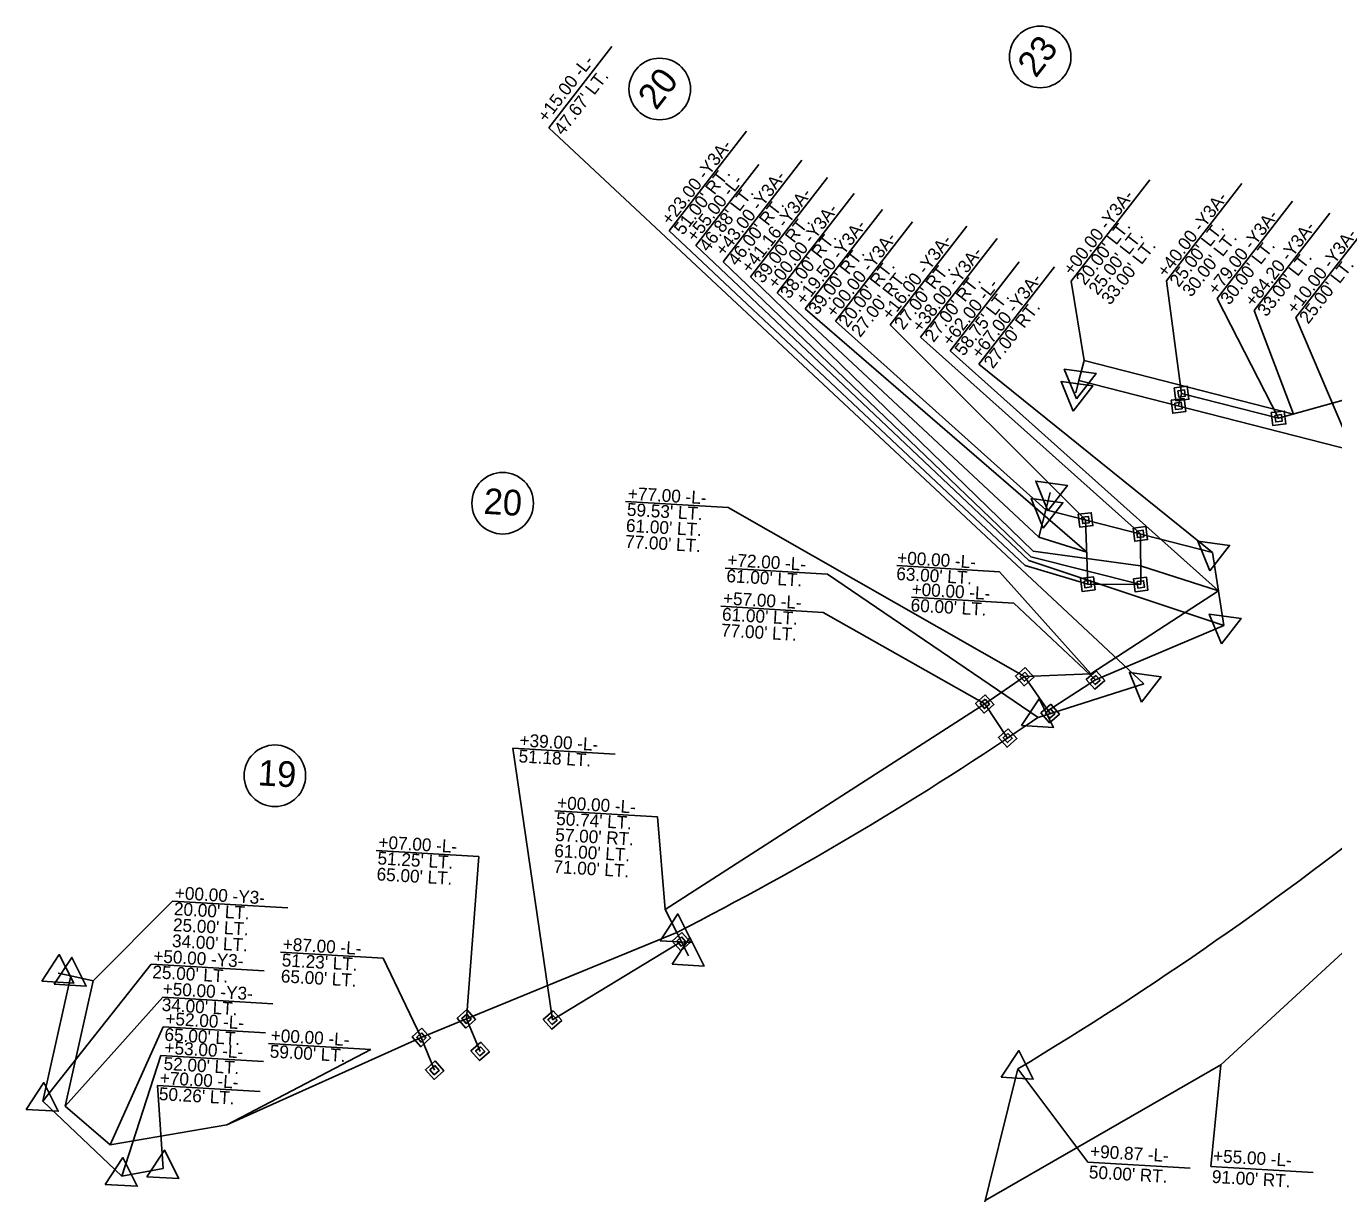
# Model space of a CAD drawing. Extents: x 2010883 to 2014849, y 442000 to 447413.
# Drawn here: x 2013533 to 2014042, y 445012 to 445467 of the extents above; entities that cross this region are included whole.
import ezdxf

# ---------------------------------------------------------------- set-up
doc = ezdxf.new("R2010")
doc.units = 0
for name, color, linetype in [('Prop Easement Construction', 7, 'Continuous'), ('Prop Easement Construction Station Offsets', 7, 'Continuous'), ('Prop Easement Permanent Drainage', 7, 'Continuous'), ('Prop Easement Permanent Drainage Station Offsets', 7, 'Continuous'), ('Prop Easement Permanent Utility', 7, 'Continuous'), ('Prop Easement Permanent Utility Station Offsets', 7, 'Continuous'), ('Prop Parcel Number CELL', 7, 'Continuous'), ('Prop Parcel Number Text', 7, 'Continuous'), ('Prop ROW Marker CELL', 7, 'Continuous'), ('Prop ROW Permanent Easement CELL', 7, 'Continuous'), ('Prop ROW RW Lines', 7, 'Continuous'), ('Prop ROW Station Offsets', 7, 'Continuous')]:
    doc.layers.add(name, color=color, linetype=linetype)

msp = doc.modelspace()

# ---------------------------------------------------------------- linework, layer by layer
at = {"layer": 'Prop Easement Construction'}
for p, q in [((2013942.7, 445328.8), (2013944.68, 445336.56)), ((2013944.68, 445336.56), (2014026.25, 445315.7)), ((2013927.09, 445267.77), (2013929.81, 445278.43)), ((2013927.09, 445267.77), (2013945.73, 445261.97)), ((2013966.71, 445256.6), (2013997.06, 445246.86)), ((2013947.4, 445214.55), (2013997.06, 445246.86)), ((2013921.55, 445213.41), (2013947.4, 445214.55)), ((2013781.47, 445122.66), (2013906.01, 445202.79)), ((2013997.94, 445062.16), (2014082.24, 445139.88)), ((2013786.01, 445113.75), (2013781.47, 445122.66)), ((2013704.09, 445080.08), (2013786.01, 445113.75)), ((2013549.97, 445096.83), (2013558.75, 445094.86)), ((2013558.75, 445094.86), (2013547.82, 445046.07)), ((2013610.79, 445038.76), (2013686.53, 445072.83)), ((2013906.21, 445009.36), (2013997.94, 445062.16)), ((2013547.82, 445046.07), (2013565.34, 445031.04)), ((2013565.34, 445031.04), (2013610.79, 445038.76))]:
    msp.add_line(p, q, dxfattribs=at)
at = {"layer": 'Prop Easement Construction Station Offsets'}
for p, q in [((2013814.73, 445369.18), (2013844.76, 445407.9)), ((2013825.15, 445363.01), (2013855.18, 445401.73)), ((2013836.1, 445356.73), (2013866.13, 445395.45)), ((2014011.02, 445356.11), (2014040.44, 445394.04)), ((2013892.56, 445340.31), (2013919.45, 445374.98)), ((2014026.25, 445315.7), (2014011.02, 445356.11)), ((2013997.06, 445246.86), (2013892.56, 445340.31)), ((2013871.82, 445256.66), (2013911.75, 445254.3)), ((2013947.4, 445214.55), (2013911.75, 445254.3)), ((2013547.82, 445046.07), (2013585.79, 445088.51)), ((2013585.79, 445088.51), (2013628.71, 445085.98)), ((2013565.34, 445031.04), (2013585.95, 445076.98)), ((2013585.95, 445076.98), (2013625.88, 445074.62)), ((2013626.99, 445070.51), (2013666.92, 445068.16)), ((2013610.79, 445038.76), (2013666.92, 445068.16)), ((2013997.94, 445062.16), (2013994.03, 445022.51)), ((2013994.03, 445022.51), (2014033.96, 445020.16))]:
    msp.add_line(p, q, dxfattribs=at)
for points in [[(2013814.73, 445369.18), (2013924.91, 445262.37), (2013924.91, 445262.37)], [(2013825.15, 445363.01), (2013927.09, 445267.77), (2013927.09, 445267.77)], [(2013836.1, 445356.73), (2013945.73, 445261.97), (2013945.73, 445261.97)], [(2013924.91, 445262.37), (2013966.71, 445256.6), (2013966.71, 445256.6)]]:
    msp.add_lwpolyline(points, dxfattribs=at)
at = {"layer": 'Prop Easement Permanent Drainage'}
for p, q in [((2013906.01, 445202.79), (2013921.55, 445213.41)), ((2013931.51, 445199.06), (2013921.55, 445213.41)), ((2013914.94, 445189.51), (2013906.01, 445202.79)), ((2013686.53, 445072.83), (2013704.09, 445080.08)), ((2013704.09, 445080.08), (2013709.44, 445067.41)), ((2013691.69, 445060.07), (2013686.53, 445072.83))]:
    msp.add_line(p, q, dxfattribs=at)
at = {"layer": 'Prop Easement Permanent Drainage Station Offsets'}
for p, q in [((2013766.11, 445281.64), (2013806.05, 445279.29)), ((2013806.05, 445279.29), (2013921.55, 445213.41)), ((2013803.17, 445240.82), (2013843.1, 445238.47)), ((2013843.1, 445238.47), (2013906.01, 445202.79)), ((2013668.96, 445145.74), (2013708.89, 445143.39)), ((2013704.09, 445080.08), (2013708.89, 445143.39)), ((2013631.67, 445106.02), (2013671.6, 445103.67)), ((2013686.53, 445072.83), (2013671.6, 445103.67))]:
    msp.add_line(p, q, dxfattribs=at)
at = {"layer": 'Prop Easement Permanent Utility'}
for p, q in [((2014020.47, 445314.08), (2014102.28, 445337)), ((2013981.45, 445318.89), (2013982.69, 445323.74)), ((2013982.69, 445323.74), (2014020.47, 445314.08)), ((2013946.15, 445249.48), (2013945.31, 445274.46)), ((2013966.76, 445249.37), (2013966.63, 445269.01)), ((2013946.15, 445249.48), (2013966.76, 445249.37)), ((2013949.15, 445212.12), (2013999.17, 445233.38)), ((2013930.68, 445200.27), (2013949.15, 445212.12)), ((2013737.64, 445079.65), (2013787.82, 445110.19))]:
    msp.add_line(p, q, dxfattribs=at)
at = {"layer": 'Prop Easement Permanent Utility Station Offsets'}
for p, q in [((2013783.11, 445387.15), (2013813.23, 445425.98)), ((2013804.09, 445375.05), (2013834.81, 445414.66)), ((2013976.76, 445367.63), (2014006.18, 445405.56)), ((2013996.51, 445360.7), (2014025.93, 445398.63)), ((2013921.7, 445256.66), (2013783.11, 445387.15)), ((2013869.18, 445350.53), (2013899.01, 445389)), ((2013881.02, 445345.72), (2013910.86, 445384.2)), ((2013923.98, 445260.15), (2013804.09, 445375.05)), ((2013976.76, 445367.63), (2013982.69, 445323.74)), ((2013996.51, 445360.7), (2014020.47, 445314.08)), ((2013869.18, 445350.53), (2013945.31, 445274.46)), ((2013881.02, 445345.72), (2013966.63, 445269.01)), ((2013966.76, 445249.37), (2013923.98, 445260.15)), ((2013946.15, 445249.48), (2013921.7, 445256.66)), ((2013877.42, 445244.4), (2013917.35, 445242.05)), ((2013949.15, 445212.12), (2013917.35, 445242.05)), ((2013722.15, 445185.59), (2013762.08, 445183.23)), ((2013737.64, 445079.65), (2013722.15, 445185.59))]:
    msp.add_line(p, q, dxfattribs=at)
at = {"layer": 'Prop Parcel Number CELL'}
for p, q in [((2013927.61, 445454.88), (2013927.61, 445454.88)), ((2013779.43, 445442.38), (2013779.43, 445442.38)), ((2013718.22, 445280.98), (2013718.22, 445280.98)), ((2013629.47, 445174.79), (2013629.47, 445174.79))]:
    msp.add_line(p, q, dxfattribs=at)
for centre in [(2013927.61, 445454.88), (2013779.43, 445442.38), (2013718.22, 445280.98), (2013629.47, 445174.79)]:
    msp.add_circle(centre, 12, dxfattribs=at)
at = {"layer": 'Prop ROW Marker CELL'}
for p, q in [((2013942.7, 445328.8), (2013942.7, 445328.8)), ((2013941.46, 445323.96), (2013941.46, 445323.96)), ((2013982.69, 445323.74), (2013982.69, 445323.74)), ((2013981.45, 445318.89), (2013981.45, 445318.89)), ((2014020.47, 445314.08), (2014020.47, 445314.08)), ((2013931.55, 445285.21), (2013931.55, 445285.21)), ((2013929.81, 445278.43), (2013929.81, 445278.43)), ((2013945.31, 445274.46), (2013945.31, 445274.46)), ((2013966.63, 445269.01), (2013966.63, 445269.01)), ((2013994.72, 445261.83), (2013994.72, 445261.83)), ((2013946.15, 445249.48), (2013946.15, 445249.48)), ((2013966.76, 445249.37), (2013966.76, 445249.37)), ((2013999.17, 445233.38), (2013999.17, 445233.38)), ((2013921.55, 445213.41), (2013921.55, 445213.41)), ((2013949.15, 445212.12), (2013949.15, 445212.12)), ((2013968.04, 445210.63), (2013968.04, 445210.63)), ((2013906.01, 445202.79), (2013906.01, 445202.79)), ((2013931.51, 445199.06), (2013931.51, 445199.06)), ((2013926.76, 445197.56), (2013926.76, 445197.56)), ((2013914.94, 445189.51), (2013914.94, 445189.51)), ((2013786.01, 445113.75), (2013786.01, 445113.75)), ((2013787.82, 445110.19), (2013787.82, 445110.19)), ((2013790.66, 445104.61), (2013790.66, 445104.61)), ((2013545.09, 445097.92), (2013545.09, 445097.92)), ((2013549.97, 445096.83), (2013549.97, 445096.83)), ((2013704.09, 445080.08), (2013704.09, 445080.08)), ((2013737.64, 445079.65), (2013737.64, 445079.65)), ((2013686.53, 445072.83), (2013686.53, 445072.83)), ((2013709.44, 445067.41), (2013709.44, 445067.41)), ((2013918.9, 445060.55), (2013918.9, 445060.55)), ((2013691.69, 445060.07), (2013691.69, 445060.07)), ((2013539.04, 445048.04), (2013539.04, 445048.04)), ((2013586.01, 445021.78), (2013586.01, 445021.78)), ((2013569.86, 445018.82), (2013569.86, 445018.82))]:
    msp.add_line(p, q, dxfattribs=at)
for points in [[(2013941.71, 445321.66), (2013937.01, 445333.22), (2013949.37, 445331.54)], [(2013940.47, 445316.82), (2013935.77, 445328.37), (2013948.13, 445326.69)], [(2013930.56, 445278.06), (2013925.86, 445289.62), (2013938.22, 445287.94)], [(2013928.83, 445271.28), (2013924.12, 445282.84), (2013936.49, 445281.16)], [(2013993.74, 445254.68), (2013989.03, 445266.24), (2014001.4, 445264.56)], [(2013998.18, 445226.24), (2013993.48, 445237.79), (2014005.84, 445236.11)], [(2013967.05, 445203.49), (2013962.35, 445215.05), (2013974.71, 445213.37)], [(2013920.31, 445194.33), (2013927.18, 445204.74), (2013932.79, 445193.59)], [(2013779.56, 445110.53), (2013786.43, 445120.94), (2013792.04, 445109.79)], [(2013784.21, 445101.38), (2013791.09, 445111.8), (2013796.69, 445100.65)], [(2013538.64, 445094.7), (2013545.51, 445105.11), (2013551.12, 445093.96)], [(2013543.52, 445093.6), (2013550.39, 445104.02), (2013556, 445092.87)], [(2013912.44, 445057.32), (2013919.32, 445067.73), (2013924.92, 445056.58)], [(2013532.59, 445044.81), (2013539.46, 445055.23), (2013545.07, 445044.08)], [(2013563.41, 445015.59), (2013570.28, 445026), (2013575.89, 445014.85)], [(2013579.56, 445018.55), (2013586.44, 445028.97), (2013592.04, 445017.82)]]:
    msp.add_lwpolyline(points, close=True, dxfattribs=at)
at = {"layer": 'Prop ROW Permanent Easement CELL'}
for points in [[(2013979.84, 445325.94), (2013984.89, 445326.58), (2013985.53, 445321.53), (2013980.48, 445320.89)], [(2013981.27, 445324.84), (2013983.79, 445325.16), (2013984.11, 445322.64), (2013981.58, 445322.32)], [(2013978.6, 445321.1), (2013983.66, 445321.74), (2013984.29, 445316.69), (2013979.24, 445316.05)], [(2013980.03, 445320), (2013982.55, 445320.32), (2013982.87, 445317.79), (2013980.35, 445317.47)], [(2014017.63, 445316.28), (2014022.68, 445316.92), (2014023.32, 445311.87), (2014018.27, 445311.23)], [(2014019.05, 445315.18), (2014021.57, 445315.5), (2014021.89, 445312.97), (2014019.37, 445312.65)], [(2013942.47, 445276.67), (2013947.52, 445277.31), (2013948.16, 445272.26), (2013943.11, 445271.62)], [(2013943.89, 445275.57), (2013946.42, 445275.88), (2013946.74, 445273.36), (2013944.21, 445273.04)], [(2013963.78, 445271.22), (2013968.83, 445271.86), (2013969.47, 445266.81), (2013964.42, 445266.17)], [(2013965.21, 445270.11), (2013967.73, 445270.43), (2013968.05, 445267.91), (2013965.52, 445267.59)], [(2013943.3, 445251.68), (2013948.36, 445252.32), (2013948.99, 445247.27), (2013943.94, 445246.63)], [(2013944.73, 445250.58), (2013947.25, 445250.9), (2013947.57, 445248.37), (2013945.05, 445248.05)], [(2013963.92, 445251.57), (2013968.97, 445252.21), (2013969.61, 445247.16), (2013964.56, 445246.52)], [(2013965.34, 445250.47), (2013967.87, 445250.79), (2013968.19, 445248.26), (2013965.66, 445247.94)], [(2013921.76, 445217), (2013925.14, 445213.2), (2013921.34, 445209.82), (2013917.96, 445213.62)], [(2013921.66, 445215.2), (2013923.35, 445213.3), (2013921.44, 445211.61), (2013919.75, 445213.51)], [(2013949.37, 445215.71), (2013952.75, 445211.91), (2013948.94, 445208.53), (2013945.56, 445212.33)], [(2013949.26, 445213.92), (2013950.95, 445212.01), (2013949.05, 445210.32), (2013947.36, 445212.22)], [(2013906.23, 445206.39), (2013909.61, 445202.58), (2013905.8, 445199.2), (2013902.42, 445203.01)], [(2013906.12, 445204.59), (2013907.81, 445202.69), (2013905.91, 445201), (2013904.22, 445202.9)], [(2013931.73, 445202.66), (2013935.11, 445198.85), (2013931.3, 445195.47), (2013927.92, 445199.27)], [(2013931.62, 445200.86), (2013933.31, 445198.96), (2013931.41, 445197.27), (2013929.72, 445199.17)], [(2013915.15, 445193.11), (2013918.53, 445189.3), (2013914.73, 445185.92), (2013911.34, 445189.73)], [(2013915.04, 445191.31), (2013916.73, 445189.41), (2013914.83, 445187.72), (2013913.14, 445189.62)], [(2013788.03, 445113.78), (2013791.42, 445109.97), (2013787.61, 445106.59), (2013784.23, 445110.4)], [(2013787.93, 445111.98), (2013789.62, 445110.08), (2013787.72, 445108.39), (2013786.03, 445110.29)], [(2013704.3, 445083.68), (2013707.69, 445079.87), (2013703.88, 445076.49), (2013700.5, 445080.3)], [(2013704.2, 445081.88), (2013705.89, 445079.98), (2013703.99, 445078.29), (2013702.3, 445080.19)], [(2013737.85, 445083.24), (2013741.23, 445079.44), (2013737.43, 445076.06), (2013734.04, 445079.86)], [(2013737.74, 445081.45), (2013739.43, 445079.54), (2013737.53, 445077.85), (2013735.84, 445079.76)], [(2013686.74, 445076.42), (2013690.13, 445072.62), (2013686.32, 445069.24), (2013682.94, 445073.04)], [(2013686.64, 445074.63), (2013688.33, 445072.72), (2013686.43, 445071.03), (2013684.73, 445072.94)], [(2013709.65, 445071.01), (2013713.03, 445067.2), (2013709.23, 445063.82), (2013705.85, 445067.62)], [(2013709.55, 445069.21), (2013711.24, 445067.31), (2013709.33, 445065.62), (2013707.64, 445067.52)], [(2013691.9, 445063.66), (2013695.28, 445059.85), (2013691.48, 445056.47), (2013688.1, 445060.28)], [(2013691.79, 445061.86), (2013693.49, 445059.96), (2013691.58, 445058.27), (2013689.89, 445060.17)]]:
    msp.add_lwpolyline(points, close=True, dxfattribs=at)
at = {"layer": 'Prop ROW RW Lines'}
for p, q in [((2013941.46, 445323.96), (2013942.7, 445328.8)), ((2013942.7, 445328.8), (2014049.27, 445301.55)), ((2013929.81, 445278.43), (2013931.55, 445285.21)), ((2013994.72, 445261.83), (2013929.81, 445278.43)), ((2013999.17, 445233.38), (2013994.72, 445261.83)), ((2013926.76, 445197.56), (2013968.04, 445210.63)), ((2013786.01, 445113.75), (2013790.66, 445104.61)), ((2013549.97, 445096.83), (2013539.04, 445048.04)), ((2013545.09, 445097.92), (2013549.97, 445096.83)), ((2013876.69, 444890.19), (2013918.9, 445060.55)), ((2013539.04, 445048.04), (2013569.86, 445018.82)), ((2013569.86, 445018.82), (2013586.01, 445021.78))]:
    msp.add_line(p, q, dxfattribs=at)
for radius, start, end in [(1350, 300.98467, 316.59253), (1239, 296.97975, 304.56042)]:
    msp.add_arc((2013223.9, 446217.91), radius, start, end, dxfattribs=at)
at = {"layer": 'Prop ROW Station Offsets'}
for p, q in [((2013736.26, 445427.3), (2013760.78, 445458.9)), ((2013736.26, 445427.3), (2013968.04, 445210.63)), ((2013793.46, 445381.36), (2013817.97, 445412.97)), ((2013939.72, 445367.5), (2013970.36, 445407.01)), ((2013847.82, 445351.9), (2013877.85, 445390.62)), ((2014027.25, 445353.3), (2014056.66, 445391.23)), ((2013793.46, 445381.36), (2013923.16, 445258.66)), ((2013903.74, 445335.19), (2013933.15, 445373.12)), ((2013939.72, 445367.5), (2013944.68, 445336.56)), ((2013929.81, 445278.43), (2013847.82, 445351.9)), ((2014027.25, 445353.3), (2014049.27, 445301.55)), ((2013903.74, 445335.19), (2013994.72, 445261.83)), ((2013804.87, 445255.73), (2013844.8, 445253.37)), ((2013923.16, 445258.66), (2013999.17, 445233.38)), ((2013844.8, 445253.37), (2013926.76, 445197.56)), ((2013738.57, 445161.13), (2013778.5, 445158.78)), ((2013778.5, 445158.78), (2013781.47, 445122.66)), ((2013589.63, 445125.96), (2013558.75, 445094.86)), ((2013589.63, 445125.96), (2013634.55, 445123.31)), ((2013539.04, 445048.04), (2013581.25, 445101.35)), ((2013581.25, 445101.35), (2013625.35, 445098.75)), ((2013569.86, 445018.82), (2013585.1, 445065.83)), ((2013585.1, 445065.83), (2013625.03, 445063.48)), ((2013946.12, 445024.29), (2013918.9, 445060.55)), ((2013583.79, 445054.12), (2013623.72, 445051.76)), ((2013586.01, 445021.78), (2013583.79, 445054.12)), ((2013946.12, 445024.29), (2013986.05, 445021.94))]:
    msp.add_line(p, q, dxfattribs=at)

# ---------------------------------------------------------------- texts
at = {"layer": 'Prop Easement Construction Station Offsets'}
for s, rotation, p in [('+41.16 -Y3A-', 52.2051, (2013814.59, 445370.2)), ('+00.00 -Y3A-', 52.2051, (2013824.89, 445364.12)), ("39.00' RT.", 52.2051, (2013819.53, 445366.37)), ('+19.50 -Y3A-', 52.2051, (2013835.84, 445357.85)), ('+84.20 -Y3A-', 52.2051, (2014010.79, 445357.18)), ("38.00' RT.", 52.2051, (2013829.83, 445360.29)), ("39.00' RT.", 52.2051, (2013840.78, 445354.02)), ("33.00' LT.", 52.2051, (2014015.73, 445353.35)), ('+62.00 -L-', 52.2051, (2013892.84, 445341.84)), ("58.75' LT.", 52.2051, (2013897.78, 445338.01)), ('+00.00 -L-', 356.6264, (2013871.81, 445257.36)), ("63.00' LT.", 356.6264, (2013871.45, 445251.12)), ('+50.00 -Y3-', 356.6264, (2013585.67, 445089.43)), ("34.00' LT.", 356.6264, (2013585.3, 445083.19)), ('+52.00 -L-', 356.6264, (2013586.73, 445077.79)), ("65.00' LT.", 356.6264, (2013586.36, 445071.55)), ('+00.00 -L-', 356.6264, (2013627.76, 445071.25)), ("59.00' LT.", 356.6264, (2013627.39, 445065.01)), ('+55.00 -L-', 356.6264, (2013994.86, 445024.3)), ("91.00' RT.", 356.6264, (2013994.38, 445016.19))]:
    msp.add_text(s, height=5, rotation=rotation, dxfattribs=at).set_placement(p)
at = {"layer": 'Prop Easement Permanent Drainage Station Offsets'}
for s, p in [('+77.00 -L-', (2013766.88, 445282.38)), ("59.53' LT.", (2013766.52, 445276.14)), ("61.00' LT.", (2013766.15, 445269.9)), ("77.00' LT.", (2013765.78, 445263.66)), ('+57.00 -L-', (2013803.94, 445241.56)), ("61.00' LT.", (2013803.57, 445235.32)), ("77.00' LT.", (2013803.21, 445229.08)), ('+07.00 -L-', (2013669.73, 445146.52)), ("51.25' LT.", (2013669.36, 445140.28)), ("65.00' LT.", (2013669, 445134.04)), ('+87.00 -L-', (2013632.44, 445106.8)), ("51.23' LT.", (2013632.07, 445100.56)), ("65.00' LT.", (2013631.7, 445094.32))]:
    msp.add_text(s, height=5, rotation=356.6264, dxfattribs=at).set_placement(p)
at = {"layer": 'Prop Easement Permanent Utility Station Offsets'}
for s, rotation, p in [('+23.00 -Y3A-', 52.2051, (2013783.51, 445389)), ("51.00' RT.", 52.2051, (2013788.45, 445385.17)), ('+43.00 -Y3A-', 52.2051, (2013804.49, 445376.9)), ("46.00' RT.", 52.2051, (2013809.43, 445373.07)), ('+40.00 -Y3A-', 52.2051, (2013976.61, 445368.67)), ('+79.00 -Y3A-', 52.2051, (2013996.36, 445361.74)), ("25.00' LT.", 52.2051, (2013981.55, 445364.84)), ('+16.00 -Y3A-', 52.2051, (2013869.3, 445352.02)), ("30.00' LT.", 52.2051, (2013986.48, 445361.01)), ("30.00' LT.", 52.2051, (2014001.3, 445357.91)), ('+38.00 -Y3A-', 52.2051, (2013881.14, 445347.22)), ("27.00' RT.", 52.2051, (2013874.24, 445348.19)), ("27.00' RT.", 52.2051, (2013886.08, 445343.38)), ('+00.00 -L-', 356.6264, (2013877.41, 445245.11)), ("60.00' LT.", 356.6264, (2013877.04, 445238.87)), ('+39.00 -L-', 356.6264, (2013724.69, 445186.26)), ('51.18 LT.', 356.6264, (2013724.32, 445180.02))]:
    msp.add_text(s, height=5, rotation=rotation, dxfattribs=at).set_placement(p)
at = {"layer": 'Prop Parcel Number Text'}
for s, rotation, p in [('23', 52.2051, (2013925.89, 445446.35)), ('20', 52.2051, (2013778.02, 445433.77)), ('20', 356.6264, (2013710.61, 445276.89)), ('19', 356.6264, (2013622.67, 445171.11))]:
    msp.add_text(s, height=10, rotation=rotation, dxfattribs=at).set_placement(p)
at = {"layer": 'Prop ROW Station Offsets'}
for s, rotation, p in [('+15.00 -L-', 52.2051, (2013735.26, 445428.99)), ("47.67' LT.", 52.2051, (2013741.68, 445424.01)), ('+55.00 -L-', 52.2051, (2013793.28, 445382.42)), ("46.88' LT.", 52.2051, (2013798.22, 445378.59)), ('+00.00 -Y3A-', 52.2051, (2013940.07, 445369.41)), ("20.00' LT.", 52.2051, (2013945.01, 445365.58)), ("25.00' LT.", 52.2051, (2013949.95, 445361.75)), ('+10.00 -Y3A-', 52.2051, (2014027.09, 445354.34)), ('+00.00 -Y3A-', 52.2051, (2013847.61, 445352.98)), ("33.00' LT.", 52.2051, (2013954.89, 445357.92)), ("20.00' RT.", 52.2051, (2013852.55, 445349.15)), ("27.00' RT.", 52.2051, (2013857.49, 445345.32)), ("25.00' LT.", 52.2051, (2014032.03, 445350.51)), ('+67.00 -Y3A-', 52.2051, (2013904.21, 445336.94)), ("27.00' RT.", 52.2051, (2013909.14, 445333.11)), ('+72.00 -L-', 356.6264, (2013805.64, 445256.5)), ("61.00' LT.", 356.6264, (2013805.28, 445250.27)), ('+00.00 -L-', 356.6264, (2013739.34, 445161.9)), ("50.74' LT.", 356.6264, (2013738.97, 445155.66)), ("57.00' RT.", 356.6264, (2013738.6, 445149.42)), ("61.00' LT.", 356.6264, (2013738.23, 445143.18)), ("71.00' LT.", 356.6264, (2013737.87, 445136.94)), ('+00.00 -Y3-', 356.6264, (2013590.41, 445126.78)), ("20.00' LT.", 356.6264, (2013590.04, 445120.54)), ("25.00' LT.", 356.6264, (2013589.67, 445114.3)), ("34.00' LT.", 356.6264, (2013589.3, 445108.06)), ('+50.00 -Y3-', 356.6264, (2013582.02, 445102.16)), ("25.00' LT.", 356.6264, (2013581.65, 445095.92)), ('+53.00 -L-', 356.6264, (2013586.39, 445066.47)), ("52.00' LT.", 356.6264, (2013586.02, 445060.23)), ('+70.00 -L-', 356.6264, (2013584.55, 445054.69)), ("50.26' LT.", 356.6264, (2013584.18, 445048.45)), ('+90.87 -L-', 356.6264, (2013946.95, 445026.08)), ("50.00' RT.", 356.6264, (2013946.47, 445017.97))]:
    msp.add_text(s, height=5, rotation=rotation, dxfattribs=at).set_placement(p)

doc.saveas('drawing.dxf')
